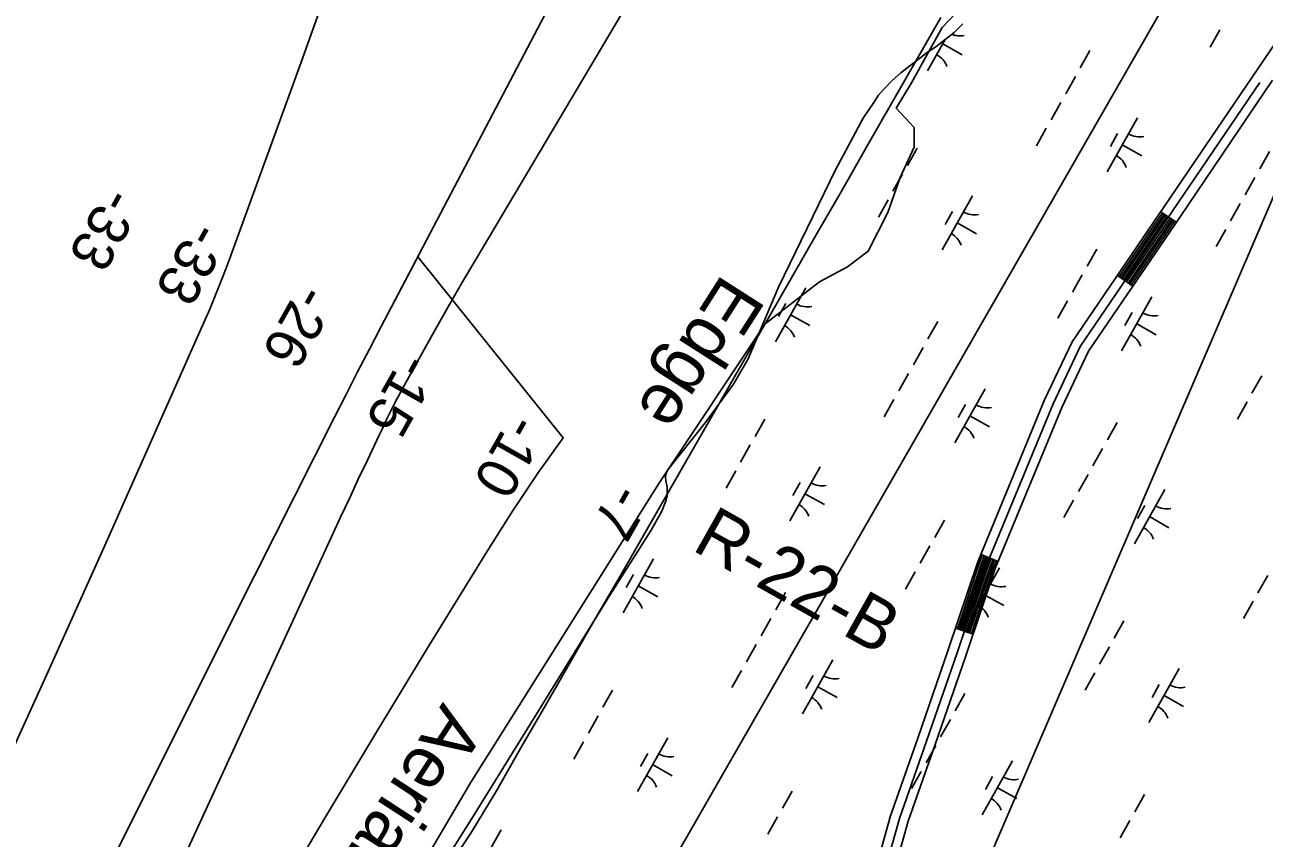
# Model space of a CAD drawing. Extents: x 3913936 to 3933962, y 195330 to 217741.
# Drawn here: x 3925651 to 3926652, y 204461 to 205118 of the extents above; entities that cross this region are included whole.
import ezdxf

# ---------------------------------------------------------------- set-up
doc = ezdxf.new("R2010")
doc.units = 0
for name, color, linetype in [('V-RIVR-EDGE', 7, 'Continuous'), ('V-RIVR-IDEN', 7, 'Continuous'), ('V-RIVR-RANG', 7, 'Continuous'), ('V-RIVR-RANG-IDEN', 7, 'Continuous'), ('V-ROAD-CNTR', 7, 'Continuous'), ('V-RRAP-FSHR', 7, 'Continuous'), ('V-TOPO-DPTH', 7, 'Continuous'), ('V-TOPO-MINR', 7, 'Continuous'), ('V-UTIL-LINE', 7, 'Continuous'), ('V-WETL-SWMP', 7, 'Continuous')]:
    doc.layers.add(name, color=color, linetype=linetype)

msp = doc.modelspace()

# ---------------------------------------------------------------- linework, layer by layer
at = {"layer": 'V-RIVR-EDGE'}
msp.add_lwpolyline([(3926461.3, 205188.9), (3926391.7, 205115.8), (3926367, 205070.9), (3926354.6, 205050.7), (3926369.2, 205034.9), (3926369.2, 205019.2), (3926358, 204994.5), (3926347.9, 204966.4), (3926332.1, 204935), (3926315.3, 204922.6), (3926292.8, 204910.3), (3926249, 204876.5), (3926163.6, 204748.5), (3926010.8, 204505.8), (3925886.1, 204293.5)], dxfattribs=at)
at = {"layer": 'V-ROAD-CNTR'}
for p, q in [((3926568.5, 204967), (3926580.9, 204958.5)), ((3926533.3, 204915.4), (3926545.7, 204906.9)), ((3926423.2, 204690.3), (3926437, 204684.5)), ((3926402.6, 204630.7), (3926416.9, 204625.9))]:
    msp.add_line(p, q, dxfattribs=at)
for points in [[(3926332.3, 204415.9), (3926350.1, 204479.4), (3926372.1, 204541.9), (3926396.8, 204613.2), (3926420.7, 204684.3), (3926474.6, 204815.1), (3926496.9, 204862), (3926571.5, 204971.4), (3926661, 205103.4)], [(3926648.3, 205071.4), (3926577.7, 204967.1), (3926503.4, 204858.3), (3926481.5, 204812), (3926427.7, 204681.7), (3926403.9, 204610.8), (3926379.2, 204539.5), (3926357.3, 204477.1), (3926339.6, 204414.2)], [(3926346.9, 204412.4), (3926364.4, 204474.9), (3926386.3, 204537), (3926411, 204608.4), (3926434.7, 204679), (3926488.4, 204809), (3926510, 204854.5), (3926583.9, 204962.9), (3926658.7, 205073.3)], [(3926534.5, 204914.5), (3926569.8, 204966.2)], [(3926535.8, 204913.7), (3926571, 204965.3)], [(3926537, 204912.8), (3926572.2, 204964.5)], [(3926538.3, 204912), (3926573.5, 204963.6)], [(3926539.5, 204911.1), (3926574.7, 204962.8)], [(3926540.7, 204910.3), (3926576, 204961.9)], [(3926542, 204909.4), (3926577.2, 204961.1)], [(3926543.2, 204908.6), (3926578.4, 204960.2)], [(3926544.5, 204907.8), (3926579.7, 204959.4)], [(3926404.1, 204630.2), (3926422.1, 204683.8), (3926424.5, 204689.7)], [(3926405.5, 204629.7), (3926423.5, 204683.2), (3926425.9, 204689.1)], [(3926406.9, 204629.3), (3926424.9, 204682.7), (3926427.3, 204688.5)], [(3926408.3, 204628.8), (3926426.3, 204682.2), (3926428.7, 204688)], [(3926409.7, 204628.3), (3926427.7, 204681.7), (3926430.1, 204687.4)], [(3926411.2, 204627.8), (3926429.1, 204681.1), (3926431.5, 204686.8)], [(3926412.6, 204627.4), (3926430.5, 204680.6), (3926432.9, 204686.3)], [(3926414, 204626.9), (3926431.9, 204680.1), (3926434.2, 204685.7)], [(3926415.4, 204626.4), (3926433.3, 204679.6), (3926435.6, 204685.1)]]:
    msp.add_lwpolyline(points, dxfattribs=at)
at = {"layer": 'V-RRAP-FSHR'}
msp.add_lwpolyline([(3925989.2, 204432), (3926011.2, 204465.2), (3926031.8, 204499.5), (3926051.7, 204534.2), (3926071.7, 204568.8), (3926091.7, 204603.5), (3926111.7, 204638.2), (3926131.7, 204672.8), (3926151.6, 204707.5), (3926171.6, 204742.1), (3926191.5, 204776.8), (3926211.4, 204811.5), (3926231.4, 204846.2), (3926251.3, 204880.9), (3926271.2, 204915.6), (3926291.1, 204950.2), (3926311.4, 204984.9), (3926331, 205019.6), (3926350.9, 205054.3), (3926370.8, 205089), (3926390.7, 205123.7)], dxfattribs=at)
at = {"layer": 'V-TOPO-DPTH'}
for points in [[(3926651.5, 206280.4), (3926415.6, 205794.7), (3926401.1, 205765), (3926386.4, 205735.5), (3926371.6, 205706), (3926356.7, 205676.6), (3926308.3, 205582), (3926269, 205505.4), (3926229.5, 205429), (3926189.8, 205352.6), (3926149.9, 205276.3), (3925938.8, 204874.3), (3925929.3, 204856.1), (3925919.8, 204837.8), (3925910.5, 204819.5), (3925901.2, 204801.2), (3925836.6, 204673), (3925795.1, 204590.5), (3925753.8, 204507.9), (3925712.5, 204425.3)], [(3925623.3, 204494.2), (3925669.8, 204595.7), (3925715.6, 204697.5), (3925794.6, 204875.2), (3925800.3, 204888.4), (3925805.9, 204901.7), (3925811.1, 204915.2), (3925816.2, 204928.7), (3925874.1, 205087.8), (3925894, 205143.8)], [(3925894, 205143.8), (3925874.1, 205087.8), (3925816.2, 204928.7), (3925811.1, 204915.2), (3925805.9, 204901.7), (3925800.3, 204888.4), (3925794.6, 204875.2), (3925715.6, 204697.5), (3925669.8, 204595.7), (3925623.3, 204494.2)], [(3925508.6, 204014.6), (3925671.4, 204342.6), (3925712.5, 204425.3), (3925753.8, 204507.9), (3925795.1, 204590.5), (3925836.6, 204673), (3925901.2, 204801.2), (3925910.5, 204819.5), (3925919.8, 204837.8), (3925929.3, 204856.1), (3925938.8, 204874.3), (3925968.4, 204930.6)], [(3925968.4, 204930.6), (3926085.8, 204784.4), (3926065.4, 204755.9), (3926044.4, 204724.3), (3926024, 204692.3), (3925977.4, 204616.4), (3925934.5, 204545.9), (3925892, 204475.2), (3925850, 204404.2), (3925808.3, 204333), (3925592.6, 203961.3)]]:
    msp.add_lwpolyline(points, dxfattribs=at)
at = {"layer": 'V-TOPO-MINR'}
for points in [[(3925712.5, 204425.3), (3925753.8, 204507.9), (3925795.1, 204590.5), (3925836.6, 204673), (3925901.2, 204801.2), (3925910.5, 204819.5), (3925919.8, 204837.8), (3925929.3, 204856.1), (3925938.8, 204874.3), (3926149.9, 205276.3), (3926189.8, 205352.6), (3926229.5, 205429), (3926269, 205505.4), (3926308.3, 205582), (3926356.7, 205676.6), (3926371.6, 205706), (3926386.4, 205735.5), (3926401.1, 205765), (3926415.6, 205794.7), (3926651.5, 206280.4)], [(3925712.7, 204300.5), (3925898.6, 204704.4), (3925905.8, 204719.9), (3925913.1, 204735.5), (3925920.3, 204751), (3925927.7, 204766.5), (3925937.2, 204786.6), (3925939.8, 204792.1), (3925942.4, 204797.5), (3925945.1, 204802.9), (3925947.8, 204808.3), (3925952.1, 204816.7), (3925953.3, 204819), (3925954.5, 204821.3), (3925973.5, 204855.7), (3925983.7, 204874), (3925994, 204892.2), (3926004.5, 204910.3), (3926015.1, 204928.3), (3926437.1, 205638.7)], [(3925623.3, 204494.2), (3925669.8, 204595.7), (3925715.6, 204697.5), (3925794.6, 204875.2), (3925800.3, 204888.4), (3925805.9, 204901.7), (3925811.1, 204915.2), (3925816.2, 204928.7), (3925874.1, 205087.8), (3925894, 205143.8)], [(3925592.6, 203961.3), (3925808.3, 204333), (3925850, 204404.2), (3925892, 204475.2), (3925934.5, 204545.9), (3925977.4, 204616.4), (3926024, 204692.3), (3926044.4, 204724.3), (3926065.4, 204755.9), (3926085.8, 204784.4)]]:
    msp.add_lwpolyline(points, dxfattribs=at)
at = {"layer": 'V-UTIL-LINE'}
for points in [[(3922259.4, 198607.7), (3922481.8, 198996.5), (3922891.2, 199568.4), (3923401.9, 200205.9), (3924391.3, 201632.9), (3925141.5, 202100.5), (3925635.9, 202689.8), (3926060.6, 203224.6), (3926266.4, 203722.1), (3926398.8, 204373.1), (3926759.4, 205212), (3927229.5, 206070.8), (3927602.5, 206766.2), (3928031.8, 207586.2)], [(3927650.4, 207012.8), (3925143.7, 202648.2), (3924419.5, 201771.6), (3924393.5, 201817.6)]]:
    msp.add_lwpolyline(points, dxfattribs=at)
at = {"layer": 'V-WETL-SWMP'}
for p, q in [((3926616.1, 205113.8), (3926608.2, 205099.8)), ((3926394.2, 205105.9), (3926380.1, 205080.7)), ((3926392.3, 205102.5), (3926408, 205093.7)), ((3926511.2, 205097), (3926503.3, 205083.1)), ((3926499.4, 205076.1), (3926491.6, 205062.1)), ((3926487.6, 205055.2), (3926479.8, 205041.2)), ((3926549.6, 205042.8), (3926525.1, 204999.2)), ((3926475.9, 205034.3), (3926468, 205020.3)), ((3926533.5, 205030), (3926527.7, 205019.6)), ((3926371.6, 205018.3), (3926363.8, 205004.4)), ((3926537.3, 205021), (3926553, 205012.2)), ((3926656.2, 205015.5), (3926648.3, 205001.6)), ((3926359.9, 204997.4), (3926352, 204983.5)), ((3926644.4, 204994.6), (3926636.6, 204980.6)), ((3926416.2, 204979.9), (3926391.7, 204936.3)), ((3926348.1, 204976.5), (3926340.3, 204962.6)), ((3926400.2, 204967.1), (3926394.3, 204956.6)), ((3926632.6, 204973.7), (3926624.8, 204959.7)), ((3926404, 204958.1), (3926419.6, 204949.2)), ((3926620.9, 204952.7), (3926613, 204938.8)), ((3926516.6, 204936.8), (3926508.8, 204922.9)), ((3926504.9, 204915.9), (3926497, 204902)), ((3926281.6, 204905.6), (3926257.1, 204862)), ((3926561.2, 204898.4), (3926536.7, 204854.8)), ((3926265.6, 204892.8), (3926259.7, 204882.3)), ((3926493.1, 204895), (3926485.3, 204881)), ((3926269.3, 204883.8), (3926285, 204875)), ((3926388.2, 204878.3), (3926380.3, 204864.3)), ((3926545.2, 204885.6), (3926539.3, 204875.1)), ((3926548.9, 204876.6), (3926564.6, 204867.7)), ((3926376.4, 204857.3), (3926368.6, 204843.4)), ((3926364.7, 204836.4), (3926356.8, 204822.5)), ((3926649.9, 204834.4), (3926642, 204820.5)), ((3926426.6, 204824.1), (3926402.1, 204780.5)), ((3926352.9, 204815.5), (3926345.1, 204801.5)), ((3926410.6, 204811.3), (3926404.7, 204800.8)), ((3926638.1, 204813.5), (3926630.3, 204799.5)), ((3926248.7, 204799.6), (3926240.8, 204785.6)), ((3926414.3, 204802.3), (3926430, 204793.4)), ((3926533.2, 204796.7), (3926525.3, 204782.8)), ((3926236.9, 204778.7), (3926229.1, 204764.7)), ((3926521.4, 204775.8), (3926513.6, 204761.9)), ((3926225.1, 204757.7), (3926217.3, 204743.8)), ((3926293.2, 204761.1), (3926268.7, 204717.5)), ((3926277.2, 204748.3), (3926271.3, 204737.9)), ((3926509.7, 204754.9), (3926501.8, 204741)), ((3926281, 204739.3), (3926296.7, 204730.5)), ((3926571.6, 204742.6), (3926547.1, 204699)), ((3926497.9, 204734), (3926490.1, 204720)), ((3926555.6, 204729.8), (3926549.7, 204719.3)), ((3926393.6, 204718.1), (3926385.8, 204704.1)), ((3926559.3, 204720.8), (3926575, 204711.9)), ((3926381.9, 204697.2), (3926374, 204683.2)), ((3926158.6, 204686.8), (3926134.1, 204643.2)), ((3926438.2, 204679.6), (3926413.7, 204636)), ((3926142.6, 204674), (3926136.7, 204663.6)), ((3926370.1, 204676.2), (3926362.3, 204662.3)), ((3926422.2, 204666.8), (3926416.3, 204656.4)), ((3926654.7, 204673.4), (3926646.8, 204659.4)), ((3926146.4, 204665), (3926162.1, 204656.2)), ((3926265.2, 204659.5), (3926257.4, 204645.5)), ((3926426, 204657.8), (3926441.7, 204649)), ((3926642.9, 204652.5), (3926635.1, 204638.5)), ((3926253.5, 204638.6), (3926245.6, 204624.6)), ((3926538.6, 204636.6), (3926530.8, 204622.6)), ((3926241.7, 204617.7), (3926233.9, 204603.7)), ((3926526.9, 204615.6), (3926519, 204601.7)), ((3926229.9, 204596.7), (3926222.1, 204582.8)), ((3926303.6, 204605.3), (3926279.1, 204561.7)), ((3926583.2, 204598.1), (3926558.7, 204554.5)), ((3926287.6, 204592.5), (3926281.7, 204582.1)), ((3926515.1, 204594.7), (3926507.3, 204580.8)), ((3926125.7, 204580.8), (3926117.8, 204566.9)), ((3926291.4, 204583.5), (3926307.1, 204574.7)), ((3926410.2, 204578), (3926402.4, 204564)), ((3926567.2, 204585.3), (3926561.3, 204574.8)), ((3926571, 204576.3), (3926586.7, 204567.5)), ((3926113.9, 204559.9), (3926106.1, 204546)), ((3926398.5, 204557.1), (3926390.6, 204543.1)), ((3926102.2, 204539), (3926094.3, 204525)), ((3926170.3, 204542.3), (3926145.8, 204498.8)), ((3926154.2, 204529.6), (3926148.3, 204519.1)), ((3926386.7, 204536.1), (3926378.9, 204522.2)), ((3926158, 204520.6), (3926173.7, 204511.7)), ((3926448.6, 204523.8), (3926424.1, 204480.2)), ((3926374.9, 204515.2), (3926367.1, 204501.3)), ((3926432.6, 204511), (3926426.7, 204500.6)), ((3926270.7, 204499.3), (3926262.8, 204485.4)), ((3926436.4, 204502), (3926452.1, 204493.2)), ((3926555.2, 204496.5), (3926547.4, 204482.5)), ((3926258.9, 204478.4), (3926251.1, 204464.4)), ((3926035.7, 204468.1), (3926011.1, 204424.5)), ((3926543.5, 204475.6), (3926535.6, 204461.6))]:
    msp.add_line(p, q, dxfattribs=at)
for points in [[(3926408.5, 205118.6), (3926401.6, 205111.6), (3926386.8, 205100.1), (3926380.1, 205095.9), (3926370.1, 205088.1), (3926365.8, 205084.7), (3926358.4, 205079), (3926351.4, 205073), (3926345.1, 205066.2), (3926340.5, 205061), (3926336.7, 205055.1), (3926328, 205042.6), (3926305.7, 205000.7), (3926259.7, 204906.1), (3926235.2, 204848.2), (3926223.3, 204827.7), (3926200.4, 204796.5), (3926170.1, 204758.4), (3926168.6, 204755), (3926168.3, 204752.2), (3926168.6, 204749.9), (3926169.7, 204744.5), (3926169.8, 204737.7), (3926168.5, 204732.8), (3926165.5, 204725.3), (3926156.9, 204709.8), (3926124.1, 204658.2), (3926060.1, 204555)], [(3926060.1, 204555), (3926011.9, 204477.2), (3925994.6, 204449.5), (3925985.2, 204436.8), (3925915.5, 204338.2), (3925881.7, 204285.3), (3925864.9, 204257.5), (3925817.1, 204163.5), (3925723.4, 203988.1), (3925651.8, 203841.6), (3925576.7, 203696.1)]]:
    msp.add_lwpolyline(points, dxfattribs=at)
for centre, start, end in [((3926406.1, 205126.5), 248.6082, 281.4297), ((3926379, 205078.3), 19.8861, 61.4297), ((3926551.1, 205045), 239.8861, 281.4297), ((3926524, 204996.8), 19.8861, 61.4297), ((3926417.7, 204982), 239.8861, 281.4297), ((3926390.6, 204933.9), 19.8861, 61.4297), ((3926283.1, 204907.7), 239.8861, 281.4297), ((3926562.7, 204900.5), 239.8861, 281.4297), ((3926256, 204859.6), 19.8861, 61.4297), ((3926535.6, 204852.4), 19.8861, 61.4297), ((3926428.1, 204826.2), 239.8861, 281.4297), ((3926401, 204778.1), 19.8861, 61.4297), ((3926294.7, 204763.3), 239.8861, 281.4297), ((3926267.6, 204715.1), 19.8861, 61.4297), ((3926573.1, 204744.7), 239.8861, 281.4297), ((3926546, 204696.6), 19.8861, 61.4297), ((3926160.1, 204689), 239.8861, 281.4297), ((3926439.7, 204681.8), 239.8861, 281.4297), ((3926133, 204640.8), 19.8861, 61.4297), ((3926412.6, 204633.6), 19.8861, 61.4297), ((3926305.1, 204607.5), 239.8861, 281.4297), ((3926584.7, 204600.3), 239.8861, 281.4297), ((3926278, 204559.3), 19.8861, 61.4297), ((3926557.6, 204552.1), 19.8861, 61.4297), ((3926171.7, 204544.5), 239.8861, 281.4297), ((3926144.7, 204496.4), 19.8861, 61.4297), ((3926450.1, 204526), 239.8861, 281.4297), ((3926423, 204477.8), 19.8861, 61.4297)]:
    msp.add_arc(centre, 17.6, start, end, dxfattribs=at)

# ---------------------------------------------------------------- texts
at = {"layer": 'V-RIVR-IDEN'}
for s, rotation, p in [('Edge', 237.4184, (3926214.6, 204918)), ('Aerial', 237.0182, (3925988.7, 204571.5))]:
    msp.add_text(s, height=42, rotation=rotation, dxfattribs=at).set_placement(p)
at = {"layer": 'V-RIVR-RANG'}
for s, rotation, p in [('-33', 240.6932, (3925717.3, 204988.7)), ('-33', 240.5483, (3925787.5, 204961)), ('-26', 240.5483, (3925873.8, 204910.5)), ('-15', 240.5483, (3925957.2, 204854.8)), ('-10', 240.5483, (3926044.2, 204805.6)), ('-7', 240.5483, (3926127.5, 204749.6))]:
    msp.add_text(s, height=33.5, rotation=rotation, dxfattribs=at).set_placement(p)
at = {"layer": 'V-RIVR-RANG-IDEN'}
msp.add_text('R-22-B', height=41.5, rotation=330.6931, dxfattribs=at).set_placement((3926188.7, 204694.4))

doc.saveas('drawing.dxf')
